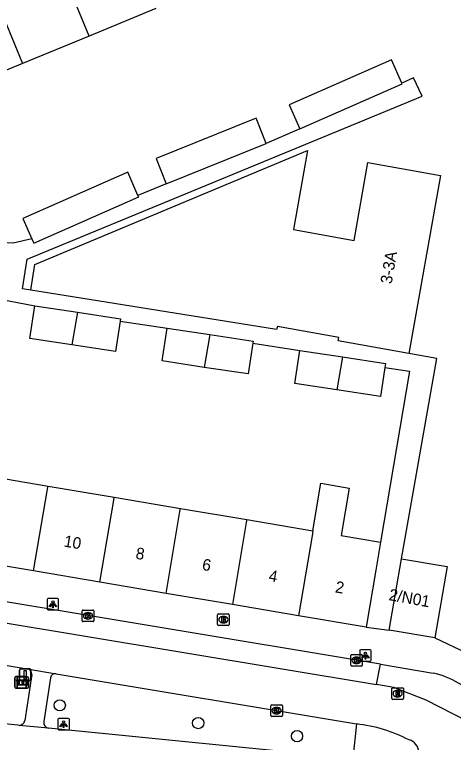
# Model space of a CAD drawing. Extents: x 160861 to 161308, y 384024 to 384878.
# Drawn here: x 161194.1 to 161232.1, y 384677.7 to 384740.7 of the extents above; entities that cross this region are included whole.
import ezdxf

# ---------------------------------------------------------------- set-up
doc = ezdxf.new("R2010")
doc.units = 0
for name, color, linetype in [('IMGEO_Afvalbak', 7, 'Continuous'), ('IMGEO_Boom', 7, 'Continuous'), ('IMGEO_Brandkraan', 7, 'Continuous'), ('IMGEO_Informatiebord', 7, 'Continuous'), ('IMGEO_Kolk', 7, 'Continuous'), ('IMGEO_Lichtpunt', 7, 'Continuous'), ('IMGEO_Muur', 7, 'Continuous'), ('IMGEO_Pand', 7, 'Continuous'), ('IMGEO_Pand_nummerreeks', 7, 'Continuous'), ('IMGEO_Rijbaan_lokaal_open', 7, 'Continuous'), ('IMGEO_Rioolput', 7, 'Continuous'), ('IMGEO_Verkeersbordpaal', 7, 'Continuous'), ('IMGEO_Verkeerseiland_gesloten', 7, 'Continuous'), ('IMGEO_Voetpad_open', 7, 'Continuous')]:
    doc.layers.add(name, color=color, linetype=linetype)

msp = doc.modelspace()

# ---------------------------------------------------------------- linework, layer by layer
at = {"layer": 'IMGEO_Afvalbak'}
for p, q in [((161194.251, 384683.384), (161195.041, 384683.384)), ((161195.041, 384683.384), (161194.251, 384683.384)), ((161194.151, 384682.484), (161194.151, 384683.284)), ((161194.151, 384683.284), (161194.151, 384682.484)), ((161195.141, 384683.284), (161195.141, 384682.484)), ((161195.141, 384682.484), (161195.141, 384683.284)), ((161195.041, 384682.384), (161194.251, 384682.384)), ((161194.251, 384682.384), (161195.041, 384682.384))]:
    msp.add_line(p, q, dxfattribs=at)
msp.add_lwpolyline([(161194.294, 384683.098), (161194.998, 384683.098), (161194.849, 384682.628), (161194.443, 384682.628), (161194.294, 384683.098)], dxfattribs=at)
for centre, start, end in [((161194.251, 384683.284), 90, 180), ((161194.251, 384683.284), 90, 180), ((161195.041, 384683.284), 0, 90), ((161195.041, 384683.284), 360, 90), ((161194.251, 384682.484), 180, 270), ((161194.251, 384682.484), 180, 270), ((161195.041, 384682.484), 270, 0), ((161195.041, 384682.484), 270, 0)]:
    msp.add_arc(centre, 0.1, start, end, dxfattribs=at)
at = {"layer": 'IMGEO_Boom'}
for centre in [(161198.043, 384680.896), (161210.024, 384679.36), (161218.574, 384678.226)]:
    msp.add_circle(centre, 0.489, dxfattribs=at)
at = {"layer": 'IMGEO_Brandkraan'}
for p, q in [((161211.702, 384687.893), (161211.702, 384688.745)), ((161211.777, 384688.819), (161212.629, 384688.819)), ((161212.19, 384688.599), (161212.215, 384688.599)), ((161212.703, 384688.745), (161212.703, 384687.893)), ((161212.629, 384687.819), (161211.777, 384687.819)), ((161212.213, 384688.039), (161212.188, 384688.039))]:
    msp.add_line(p, q, dxfattribs=at)
for points in [[(161211.702, 384687.893), (161211.702, 384688.745)], [(161211.777, 384688.819), (161212.629, 384688.819)], [(161212.05, 384688.519), (161212.05, 384688.119), (161212.263, 384688.119)], [(161212.281, 384688.519), (161212.05, 384688.519)], [(161212.229, 384688.438), (161212.175, 384688.438), (161212.175, 384688.362)], [(161212.703, 384688.745), (161212.703, 384687.893)], [(161212.629, 384687.819), (161211.777, 384687.819)], [(161212.175, 384688.362), (161212.228, 384688.362)], [(161212.237, 384688.286), (161212.175, 384688.286), (161212.175, 384688.205)], [(161212.175, 384688.205), (161212.237, 384688.205)]]:
    msp.add_lwpolyline(points, dxfattribs=at)
for centre, radius, start, end in [((161211.779, 384688.743), 0.0765, 91.55205, 178.44795), ((161211.779, 384688.743), 0.0765, 91.55205, 178.44795), ((161212.23, 384688.4), 0.0379, 267.82845, 90.93552), ((161212.285, 384688.374), 0.145, 59.4692, 91.53667), ((161212.31, 384688.421), 0.0922, 285.51372, 58.15012), ((161212.627, 384688.743), 0.0765, 1.55205, 88.44795), ((161212.627, 384688.743), 0.0765, 1.55205, 88.44795), ((161211.779, 384687.895), 0.0765, 181.55205, 268.44795), ((161211.779, 384687.895), 0.0765, 181.55205, 268.44795), ((161212.238, 384688.245), 0.0404, 269.87594, 90.50774), ((161212.269, 384688.37), 0.251, 268.66757, 293.53466), ((161212.315, 384688.229), 0.105, 301.31148, 78.98903), ((161212.627, 384687.895), 0.0765, 271.55205, 358.44795), ((161212.627, 384687.895), 0.0765, 271.55205, 358.44795)]:
    msp.add_arc(centre, radius, start, end, dxfattribs=at)
for centre, major_axis, ratio, start_param, end_param in [((161212.189, 384688.319), (-0.387, 0.002), 0.722429, 4.712389, 7.853982), ((161212.214, 384688.319), (-0.39, 0.002), 0.717154, 1.570796, 4.712389)]:
    msp.add_ellipse(centre, major_axis=major_axis, ratio=ratio, start_param=start_param, end_param=end_param, dxfattribs=at)
at = {"layer": 'IMGEO_Informatiebord'}
for p, q in [((161194.457, 384683.375), (161195.247, 384683.375)), ((161195.247, 384683.375), (161194.457, 384683.375)), ((161194.357, 384682.475), (161194.357, 384683.275)), ((161194.357, 384683.275), (161194.357, 384682.475)), ((161195.347, 384683.275), (161195.347, 384682.475)), ((161195.347, 384682.475), (161195.347, 384683.275)), ((161195.247, 384682.375), (161194.457, 384682.375)), ((161194.457, 384682.375), (161195.247, 384682.375))]:
    msp.add_line(p, q, dxfattribs=at)
for points in [[(161194.458, 384683.107), (161195.246, 384683.107), (161195.246, 384682.643), (161194.458, 384682.643), (161194.458, 384683.107)], [(161194.523, 384683.042), (161194.523, 384682.708), (161194.798, 384682.708), (161194.799, 384682.921), (161194.903, 384682.922), (161194.904, 384682.708), (161195.181, 384682.708), (161195.181, 384683.042), (161194.905, 384683.042), (161194.905, 384682.962), (161194.799, 384682.962), (161194.799, 384683.042), (161194.523, 384683.042)]]:
    msp.add_lwpolyline(points, dxfattribs=at)
for centre, start, end in [((161194.457, 384683.275), 90, 180), ((161194.457, 384683.275), 90, 180), ((161195.247, 384683.275), 0, 90), ((161195.247, 384683.275), 360, 90), ((161194.457, 384682.475), 180, 270), ((161194.457, 384682.475), 180, 270), ((161195.247, 384682.475), 270, 0), ((161195.247, 384682.475), 270, 0)]:
    msp.add_arc(centre, 0.1, start, end, dxfattribs=at)
at = {"layer": 'IMGEO_Kolk'}
for p, q in [((161199.984, 384688.22), (161199.984, 384689.072)), ((161200.059, 384689.146), (161200.911, 384689.146)), ((161200.985, 384689.072), (161200.985, 384688.22)), ((161200.472, 384688.926), (161200.497, 384688.926)), ((161200.911, 384688.146), (161200.059, 384688.146)), ((161200.495, 384688.366), (161200.47, 384688.366)), ((161223.299, 384685.298), (161224.151, 384685.298)), ((161223.224, 384684.372), (161223.224, 384685.224)), ((161223.712, 384685.078), (161223.737, 384685.078)), ((161224.225, 384685.224), (161224.225, 384684.372)), ((161224.151, 384684.298), (161223.299, 384684.298)), ((161223.735, 384684.518), (161223.71, 384684.518)), ((161216.309, 384680.014), (161216.309, 384680.866)), ((161216.384, 384680.94), (161217.236, 384680.94)), ((161217.31, 384680.866), (161217.31, 384680.014)), ((161216.797, 384680.72), (161216.822, 384680.72)), ((161217.236, 384679.94), (161216.384, 384679.94)), ((161216.82, 384680.16), (161216.795, 384680.16))]:
    msp.add_line(p, q, dxfattribs=at)
for points in [[(161199.984, 384688.22), (161199.984, 384689.072)], [(161200.059, 384689.146), (161200.911, 384689.146)], [(161200.985, 384689.072), (161200.985, 384688.22)], [(161200.305, 384688.846), (161200.428, 384688.846), (161200.428, 384688.695), (161200.558, 384688.846), (161200.722, 384688.846), (161200.576, 384688.695), (161200.729, 384688.446), (161200.577, 384688.446), (161200.492, 384688.61), (161200.428, 384688.543), (161200.428, 384688.446), (161200.305, 384688.446), (161200.305, 384688.846)], [(161200.911, 384688.146), (161200.059, 384688.146)], [(161223.299, 384685.298), (161224.151, 384685.298)], [(161223.224, 384684.372), (161223.224, 384685.224)], [(161223.545, 384684.998), (161223.668, 384684.998), (161223.668, 384684.847), (161223.798, 384684.998), (161223.962, 384684.998), (161223.816, 384684.847), (161223.969, 384684.598), (161223.817, 384684.598), (161223.732, 384684.762), (161223.668, 384684.695), (161223.668, 384684.598), (161223.545, 384684.598), (161223.545, 384684.998)], [(161224.225, 384685.224), (161224.225, 384684.372)], [(161224.151, 384684.298), (161223.299, 384684.298)], [(161216.309, 384680.014), (161216.309, 384680.866)], [(161216.384, 384680.94), (161217.236, 384680.94)], [(161217.31, 384680.866), (161217.31, 384680.014)], [(161216.63, 384680.64), (161216.753, 384680.64), (161216.753, 384680.489), (161216.883, 384680.64), (161217.047, 384680.64), (161216.901, 384680.489), (161217.054, 384680.24), (161216.902, 384680.24), (161216.817, 384680.404), (161216.753, 384680.337), (161216.753, 384680.24), (161216.63, 384680.24), (161216.63, 384680.64)], [(161217.236, 384679.94), (161216.384, 384679.94)]]:
    msp.add_lwpolyline(points, dxfattribs=at)
for centre, start, end in [((161200.061, 384689.07), 91.55205, 178.44795), ((161200.061, 384689.07), 91.55205, 178.44795), ((161200.909, 384689.07), 1.55205, 88.44795), ((161200.909, 384689.07), 1.55205, 88.44795), ((161200.061, 384688.222), 181.55205, 268.44795), ((161200.061, 384688.222), 181.55205, 268.44795), ((161200.909, 384688.222), 271.55205, 358.44795), ((161200.909, 384688.222), 271.55205, 358.44795), ((161223.301, 384685.222), 91.55205, 178.44795), ((161223.301, 384685.222), 91.55205, 178.44795), ((161224.149, 384685.222), 1.55205, 88.44795), ((161224.149, 384685.222), 1.55205, 88.44795), ((161223.301, 384684.374), 181.55205, 268.44795), ((161223.301, 384684.374), 181.55205, 268.44795), ((161224.149, 384684.374), 271.55205, 358.44795), ((161224.149, 384684.374), 271.55205, 358.44795), ((161216.386, 384680.864), 91.55205, 178.44795), ((161216.386, 384680.864), 91.55205, 178.44795), ((161217.234, 384680.864), 1.55205, 88.44795), ((161217.234, 384680.864), 1.55205, 88.44795), ((161216.386, 384680.016), 181.55205, 268.44795), ((161216.386, 384680.016), 181.55205, 268.44795), ((161217.234, 384680.016), 271.55205, 358.44795), ((161217.234, 384680.016), 271.55205, 358.44795)]:
    msp.add_arc(centre, 0.0765, start, end, dxfattribs=at)
for centre, major_axis, ratio, start_param, end_param in [((161200.471, 384688.646), (-0.387, 0.002), 0.722429, 4.712389, 7.853982), ((161200.496, 384688.646), (-0.39, 0.002), 0.717154, 1.570796, 4.712389), ((161223.711, 384684.798), (-0.387, 0.002), 0.722429, 4.712389, 7.853982), ((161223.736, 384684.798), (-0.39, 0.002), 0.717154, 1.570796, 4.712389), ((161216.796, 384680.44), (-0.387, 0.002), 0.722429, 4.712389, 7.853982), ((161216.821, 384680.44), (-0.39, 0.002), 0.717154, 1.570796, 4.712389)]:
    msp.add_ellipse(centre, major_axis=major_axis, ratio=ratio, start_param=start_param, end_param=end_param, dxfattribs=at)
at = {"layer": 'IMGEO_Lichtpunt'}
for p, q in [((161196.949, 384690.057), (161196.949, 384689.25)), ((161196.949, 384690.057), (161196.949, 384689.25)), ((161197.851, 384690.152), (161197.043, 384690.152)), ((161197.851, 384690.152), (161197.043, 384690.152)), ((161197.945, 384689.25), (161197.945, 384690.057)), ((161197.945, 384689.25), (161197.945, 384690.057)), ((161197.043, 384689.156), (161197.851, 384689.156)), ((161197.043, 384689.156), (161197.851, 384689.156)), ((161223.997, 384685.613), (161223.997, 384684.806)), ((161223.997, 384685.613), (161223.997, 384684.806)), ((161224.899, 384685.708), (161224.091, 384685.708)), ((161224.899, 384685.708), (161224.091, 384685.708)), ((161224.993, 384684.806), (161224.993, 384685.613)), ((161224.993, 384684.806), (161224.993, 384685.613)), ((161224.091, 384684.712), (161224.899, 384684.712)), ((161224.091, 384684.712), (161224.899, 384684.712)), ((161197.876, 384679.668), (161197.876, 384678.861)), ((161197.876, 384679.668), (161197.876, 384678.861)), ((161198.778, 384679.763), (161197.97, 384679.763)), ((161198.778, 384679.763), (161197.97, 384679.763)), ((161198.872, 384678.861), (161198.872, 384679.668)), ((161198.872, 384678.861), (161198.872, 384679.668)), ((161197.97, 384678.767), (161198.778, 384678.767)), ((161197.97, 384678.767), (161198.778, 384678.767))]:
    msp.add_line(p, q, dxfattribs=at)
for points in [[(161197.323, 384689.721), (161197.362, 384689.693), (161197.174, 384689.431), (161197.136, 384689.458), (161197.323, 384689.721)], [(161197.425, 384689.673), (161197.472, 384689.673), (161197.472, 384689.351), (161197.425, 384689.351), (161197.425, 384689.673)], [(161197.535, 384689.693), (161197.573, 384689.72), (161197.76, 384689.458), (161197.721, 384689.43), (161197.535, 384689.693)], [(161224.371, 384685.277), (161224.41, 384685.249), (161224.222, 384684.987), (161224.184, 384685.014), (161224.371, 384685.277)], [(161224.583, 384685.249), (161224.621, 384685.276), (161224.808, 384685.014), (161224.769, 384684.986), (161224.583, 384685.249)], [(161224.473, 384685.229), (161224.52, 384685.229), (161224.52, 384684.907), (161224.473, 384684.907), (161224.473, 384685.229)], [(161198.25, 384679.332), (161198.289, 384679.304), (161198.101, 384679.042), (161198.063, 384679.069), (161198.25, 384679.332)], [(161198.352, 384679.284), (161198.399, 384679.284), (161198.399, 384678.962), (161198.352, 384678.962), (161198.352, 384679.284)], [(161198.462, 384679.304), (161198.5, 384679.331), (161198.687, 384679.069), (161198.648, 384679.041), (161198.462, 384679.304)]]:
    msp.add_lwpolyline(points, dxfattribs=at)
for centre in [(161197.448, 384689.855), (161224.496, 384685.411), (161198.375, 384679.466)]:
    msp.add_circle(centre, 0.0994, dxfattribs=at)
for centre, start, end in [((161197.043, 384690.057), 90, 180), ((161197.043, 384690.057), 90, 180), ((161197.851, 384690.057), 0, 90), ((161197.851, 384690.057), 0, 90), ((161197.043, 384689.25), 180, 270), ((161197.043, 384689.25), 180, 270), ((161197.851, 384689.25), 270, 0), ((161197.851, 384689.25), 270, 360), ((161224.091, 384685.613), 90, 180), ((161224.091, 384685.613), 90, 180), ((161224.899, 384685.613), 0, 90), ((161224.899, 384685.613), 0, 90), ((161224.091, 384684.806), 180, 270), ((161224.091, 384684.806), 180, 270), ((161224.899, 384684.806), 270, 0), ((161224.899, 384684.806), 270, 360), ((161197.97, 384679.668), 90, 180), ((161197.97, 384679.668), 90, 180), ((161198.778, 384679.668), 0, 90), ((161198.778, 384679.668), 0, 90), ((161197.97, 384678.861), 180, 270), ((161197.97, 384678.861), 180, 270), ((161198.778, 384678.861), 270, 0), ((161198.778, 384678.861), 270, 360)]:
    msp.add_arc(centre, 0.0946, start, end, dxfattribs=at)
at = {"layer": 'IMGEO_Muur'}
msp.add_lwpolyline([(161230.514, 384686.747), (161238.896, 384682.765), (161241.061, 384682.538)], dxfattribs=at)
at = {"layer": 'IMGEO_Pand'}
for points in [[(161200.592, 384738.846), (161196.67, 384748.363)], [(161190.891, 384745.982), (161194.813, 384736.465)], [(161206.37, 384741.228), (161200.592, 384738.846)], [(161200.592, 384738.846), (161194.813, 384736.465)], [(161194.813, 384736.465), (161189.034, 384734.084)], [(161227.646, 384734.774), (161226.754, 384736.794), (161217.891, 384732.88), (161218.807, 384730.805)], [(161218.807, 384730.805), (161227.67, 384734.719), (161227.646, 384734.774)], [(161215.915, 384729.538), (161215.035, 384731.724), (161206.374, 384728.237), (161207.254, 384726.052)], [(161207.254, 384726.052), (161215.915, 384729.538)], [(161195.533, 384716.847), (161195.889, 384719.063), (161219.474, 384728.931), (161218.258, 384722.091), (161223.516, 384721.156), (161224.714, 384727.895), (161231.004, 384726.776), (161228.263, 384711.354)], [(161204.813, 384725.054), (161203.935, 384727.049), (161194.861, 384723.053), (161195.637, 384721.289)], [(161195.637, 384721.289), (161195.798, 384720.923), (161204.873, 384724.919), (161204.813, 384725.054)], [(161228.263, 384711.354), (161222.144, 384712.442), (161222.198, 384712.745), (161216.898, 384713.688), (161216.814, 384713.427), (161195.533, 384716.847)], [(161199.092, 384712.098), (161195.448, 384712.651), (161195.881, 384715.501)], [(161195.881, 384715.501), (161199.572, 384714.941)], [(161199.572, 384714.941), (161199.092, 384712.098)], [(161199.572, 384714.941), (161203.309, 384714.374), (161203.278, 384714.169)], [(161203.278, 384714.169), (161202.876, 384711.524), (161199.092, 384712.098)], [(161210.554, 384710.161), (161206.913, 384710.713), (161207.346, 384713.563)], [(161207.346, 384713.563), (161211.035, 384713.003)], [(161211.035, 384713.003), (161210.554, 384710.161)], [(161211.035, 384713.003), (161214.774, 384712.436), (161214.745, 384712.243)], [(161214.745, 384712.243), (161214.341, 384709.586), (161210.554, 384710.161)], [(161222.019, 384708.223), (161218.377, 384708.775), (161218.81, 384711.625)], [(161218.81, 384711.625), (161222.499, 384711.065)], [(161222.499, 384711.065), (161222.019, 384708.223)], [(161222.499, 384711.065), (161226.238, 384710.498), (161226.186, 384710.157)], [(161226.186, 384710.157), (161225.805, 384707.648), (161222.019, 384708.223)], [(161191.294, 384700.85), (161197.026, 384699.881)], [(161195.783, 384692.528), (161196.983, 384699.626), (161197.026, 384699.881)], [(161197.026, 384699.881), (161202.758, 384698.912)], [(161219.955, 384696.005), (161220.65, 384700.121), (161223.086, 384699.709), (161222.391, 384695.593), (161225.803, 384695.017)], [(161201.516, 384691.559), (161202.715, 384698.657), (161202.758, 384698.912)], [(161202.758, 384698.912), (161208.49, 384697.943)], [(161207.248, 384690.59), (161208.447, 384697.687), (161208.49, 384697.943)], [(161208.49, 384697.943), (161214.222, 384696.974)], [(161214.222, 384696.974), (161214.179, 384696.718), (161212.98, 384689.621)], [(161214.222, 384696.974), (161219.955, 384696.005)], [(161219.955, 384696.005), (161219.911, 384695.748), (161218.712, 384688.652)], [(161225.803, 384695.017), (161225.394, 384692.595), (161224.56, 384687.664)], [(161195.783, 384692.528), (161190.051, 384693.497)], [(161226.561, 384687.415), (161227.603, 384693.584)], [(161227.603, 384693.584), (161231.556, 384692.916), (161230.514, 384686.747)], [(161201.516, 384691.559), (161195.783, 384692.528)], [(161207.248, 384690.59), (161201.516, 384691.559)], [(161212.98, 384689.621), (161207.248, 384690.59)], [(161218.712, 384688.652), (161212.98, 384689.621)], [(161224.56, 384687.664), (161218.712, 384688.652)], [(161230.514, 384686.747), (161226.561, 384687.415)]]:
    msp.add_lwpolyline(points, dxfattribs=at)
at = {"layer": 'IMGEO_Rijbaan_lokaal_open'}
for points in [[(161183.564, 384689.645), (161225.466, 384682.697)], [(161182.965, 384686.099), (161195.22, 384684.061)], [(161194.533, 384679.161), (161194.415, 384679.172), (161147.028, 384683.998), (161144.055, 384684.484), (161143.417, 384684.619), (161143.107, 384684.751)], [(161195.22, 384684.061), (161197.732, 384683.627)], [(161225.466, 384682.697), (161225.789, 384684.447)], [(161225.789, 384684.447), (161230.353, 384683.679)], [(161197.732, 384683.627), (161223.711, 384679.283)], [(161238.021, 384677.113), (161229.746, 384681.332), (161226.945, 384682.439), (161225.466, 384682.697)], [(161197.076, 384678.923), (161194.533, 384679.161)], [(161223.394, 384676.278), (161197.076, 384678.923)]]:
    msp.add_lwpolyline(points, dxfattribs=at)
for centre, radius, start, end in [((161229.014, 384677.016), 6.796, 38.69718, 78.63443), ((161222.302, 384666.457), 12.903, 62.44012, 83.73085), ((161228.038, 384676.872), 1.05, 358.63005, 77.12748)]:
    msp.add_arc(centre, radius, start, end, dxfattribs=at)
at = {"layer": 'IMGEO_Rioolput'}
for p, q in [((161226.782, 384681.487), (161226.782, 384682.339)), ((161226.857, 384682.413), (161227.709, 384682.413)), ((161227.27, 384682.193), (161227.295, 384682.193)), ((161227.783, 384682.339), (161227.783, 384681.487)), ((161227.293, 384681.633), (161227.268, 384681.633)), ((161227.709, 384681.413), (161226.857, 384681.413))]:
    msp.add_line(p, q, dxfattribs=at)
for points in [[(161226.782, 384681.487), (161226.782, 384682.339)], [(161226.857, 384682.413), (161227.709, 384682.413)], [(161227.371, 384682.111), (161227.119, 384682.113), (161227.119, 384681.713)], [(161227.783, 384682.339), (161227.783, 384681.487)], [(161227.119, 384681.713), (161227.243, 384681.713), (161227.243, 384681.875), (161227.254, 384681.875)], [(161227.297, 384682.032), (161227.243, 384682.032), (161227.243, 384681.951)], [(161227.243, 384681.951), (161227.295, 384681.951)], [(161227.301, 384681.846), (161227.372, 384681.713), (161227.512, 384681.713), (161227.447, 384681.839)], [(161227.709, 384681.413), (161226.857, 384681.413)]]:
    msp.add_lwpolyline(points, dxfattribs=at)
for centre, radius, start, end in [((161226.859, 384682.337), 0.0765, 91.55205, 178.44795), ((161226.859, 384682.337), 0.0765, 91.55205, 178.44795), ((161227.37, 384682.001), 0.109, 350.36119, 89.41601), ((161227.707, 384682.337), 0.0765, 1.55205, 88.44795), ((161227.707, 384682.337), 0.0765, 1.55205, 88.44795), ((161226.859, 384681.489), 0.0765, 181.55205, 268.44795), ((161226.859, 384681.489), 0.0765, 181.55205, 268.44795), ((161227.253, 384681.822), 0.0533, 26.02933, 88.69889), ((161227.279, 384682.14), 0.19, 274.7715, 282.96867), ((161227.303, 384681.936), 0.0964, 77.00612, 93.18647), ((161227.317, 384681.993), 0.0378, 276.66336, 79.67722), ((161227.368, 384682.001), 0.112, 277.58423, 350.98172), ((161227.352, 384681.786), 0.108, 29.51342, 73.79051), ((161227.707, 384681.489), 0.0765, 271.55205, 358.44795), ((161227.707, 384681.489), 0.0765, 271.55205, 358.44795)]:
    msp.add_arc(centre, radius, start, end, dxfattribs=at)
for centre, major_axis, ratio, start_param, end_param in [((161227.269, 384681.913), (-0.387, 0.002), 0.722429, 4.712389, 7.853982), ((161227.294, 384681.913), (-0.39, 0.002), 0.717154, 1.570796, 4.712389)]:
    msp.add_ellipse(centre, major_axis=major_axis, ratio=ratio, start_param=start_param, end_param=end_param, dxfattribs=at)
at = {"layer": 'IMGEO_Verkeersbordpaal'}
for p, q in [((161194.657, 384684.042), (161195.447, 384684.042)), ((161195.447, 384684.042), (161194.657, 384684.042)), ((161194.557, 384683.142), (161194.557, 384683.942)), ((161194.557, 384683.942), (161194.557, 384683.142)), ((161195.547, 384683.942), (161195.547, 384683.142)), ((161195.547, 384683.142), (161195.547, 384683.942)), ((161195.447, 384683.042), (161194.657, 384683.042)), ((161194.657, 384683.042), (161195.447, 384683.042))]:
    msp.add_line(p, q, dxfattribs=at)
msp.add_lwpolyline([(161194.977, 384683.917), (161195.127, 384683.917), (161195.127, 384683.167), (161194.977, 384683.167), (161194.977, 384683.917)], dxfattribs=at)
for centre, start, end in [((161194.657, 384683.942), 90, 180), ((161194.657, 384683.942), 90, 180), ((161195.447, 384683.942), 0, 90), ((161195.447, 384683.942), 360, 90), ((161194.657, 384683.142), 180, 270), ((161194.657, 384683.142), 180, 270), ((161195.447, 384683.142), 270, 0), ((161195.447, 384683.142), 270, 0)]:
    msp.add_arc(centre, 0.1, start, end, dxfattribs=at)
at = {"layer": 'IMGEO_Verkeerseiland_gesloten'}
msp.add_lwpolyline([(161223.711, 384679.283), (161223.394, 384676.278)], dxfattribs=at)
at = {"layer": 'IMGEO_Voetpad_open'}
for points in [[(161195.533, 384716.847), (161194.816, 384716.962), (161195.23, 384719.539), (161229.402, 384733.629), (161228.652, 384735.242), (161227.646, 384734.774)], [(161218.807, 384730.805), (161215.915, 384729.538)], [(161207.254, 384726.052), (161204.813, 384725.054)], [(161195.637, 384721.289), (161194.025, 384720.903), (161192.998, 384720.977)], [(161192.238, 384716.183), (161195.881, 384715.501)], [(161203.278, 384714.169), (161207.346, 384713.563)], [(161214.745, 384712.243), (161218.81, 384711.625)], [(161227.603, 384693.584), (161230.675, 384710.927), (161228.263, 384711.354)], [(161226.186, 384710.157), (161228.305, 384709.835), (161225.803, 384695.017)], [(161225.789, 384684.447), (161146.911, 384697.588)], [(161224.56, 384687.664), (161226.561, 384687.415)], [(161230.514, 384686.747), (161238.896, 384682.765), (161241.061, 384682.538)], [(161195.637, 384683.561), (161195.015, 384679.568)], [(161197.247, 384683.29), (161196.676, 384679.505)]]:
    msp.add_lwpolyline(points, dxfattribs=at)
for centre, radius, start, end in [((161195.127, 384683.56), 0.51, 0.12267, 79.53355), ((161197.675, 384683.192), 0.439, 82.52075, 167.0659), ((161194.519, 384679.667), 0.506, 271.60747, 348.74792), ((161197.136, 384679.393), 0.473, 166.25606, 262.74427)]:
    msp.add_arc(centre, radius, start, end, dxfattribs=at)

# ---------------------------------------------------------------- texts
at = {"layer": 'IMGEO_Pand_nummerreeks'}
for s, rotation, p in [('3-3A', 80.46154, (161226.764, 384717.332)), ('10', 350.40667, (161198.346, 384694.65)), ('8', 350.40667, (161204.559, 384693.601)), ('6', 350.40667, (161210.313, 384692.628)), ('4', 350.40667, (161216.071, 384691.654)), ('2', 350.40869, (161221.827, 384690.682)), ('2/N01', 349.69515, (161226.468, 384690.016))]:
    msp.add_text(s, height=1, rotation=rotation, dxfattribs=at).set_placement(p)

doc.saveas('drawing.dxf')
